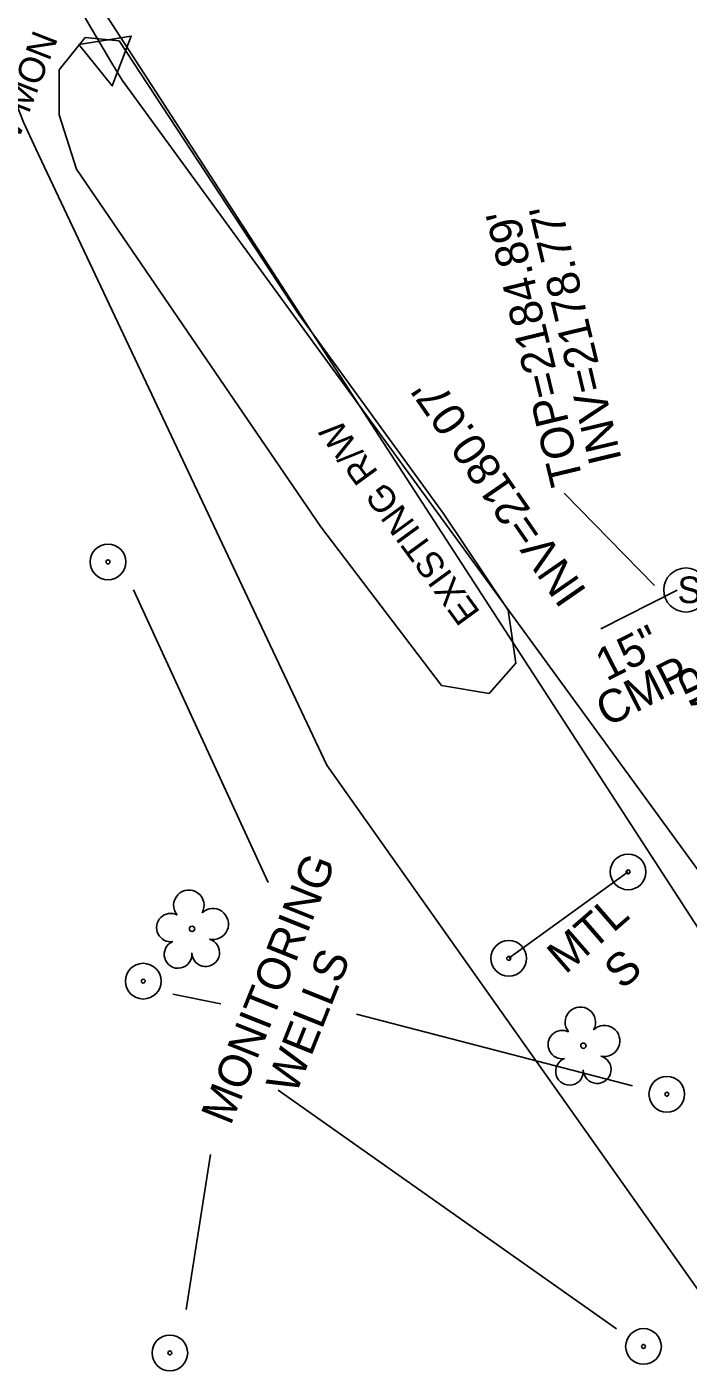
# Model space of a CAD drawing. Extents: x 945964 to 948456, y 631061 to 636061.
# Drawn here: x 946773.8 to 946854.6, y 633631 to 633795.4 of the extents above; entities that cross this region are included whole.
import ezdxf

# ---------------------------------------------------------------- set-up
doc = ezdxf.new("R2010")
doc.units = 0
for name, color, linetype in [('Exist Other Culture Fence Line', 7, 'Continuous'), ('Exist Other Culture Located Object CELL', 7, 'Continuous'), ('Exist Other Culture Located Object Leader', 7, 'Continuous'), ('Exist Other Culture Located Object Text', 7, 'Continuous'), ('Exist Other Culture Sign CELL', 7, 'Continuous'), ('Exist Other Culture Sign Text', 7, 'Continuous'), ('Exist Right of Way Line', 7, 'Continuous'), ('Exist Right of Way Line Text', 7, 'Continuous'), ('Exist Right of Way Monument CELL', 7, 'Continuous'), ('Exist Right of Way Monument Text', 7, 'Continuous'), ('Exist Structure Minor Pipes CMP 15 Inch', 7, 'Continuous'), ('Exist Structure Minor Pipes CMP 15 Inch Invert', 7, 'Continuous'), ('Exist Structure Minor Pipes CMP 15 Inch Text', 7, 'Continuous'), ('Exist Structure Minor Storm Sewer Manhole CELL', 7, 'Continuous'), ('Exist Structure Minor Storm Sewer Manhole Leader', 7, 'Continuous'), ('Exist Structure Minor Storm Sewer Manhole Text', 7, 'Continuous'), ('Exist Utilities Water UG Line SUE', 7, 'Continuous'), ('Exist Vegetation Tree CELL', 7, 'Continuous'), ('Exist Vegetation Woods Line', 7, 'Continuous'), ('Old_Level_4', 7, 'Continuous')]:
    doc.layers.add(name, color=color, linetype=linetype)

# ---------------------------------------------------------------- blocks, each defined once
blk = doc.blocks.new('EXIST STRUCTURE MINOR STORM SEWER MANHOLE')
at = {"layer": 'Exist Structure Minor Storm Sewer Manhole CELL'}
blk.add_circle((0, 0), 0.0539, dxfattribs=at)
blk.add_text('S', height=0.065, dxfattribs=at).set_placement((-0.0206, -0.032))

msp = doc.modelspace()

# ---------------------------------------------------------------- linework, layer by layer
at = {"layer": 'Exist Other Culture Fence Line'}
msp.add_lwpolyline([(946878.27, 633607.67), (946888.64, 633643.47), (946880.77, 633649.9), (946866.85, 633668.33), (946820.19, 633740.22), (946774.6, 633810.54), (946747.06, 633866.82), (946715.89, 633963.4), (946695.94, 634031.44), (946673.26, 634115.84), (946613.35, 634334.02), (946562.75, 634516.44)], dxfattribs=at)
at = {"layer": 'Exist Other Culture Located Object CELL'}
for centre, radius in [((946783.68, 633730.09), 2.18), ((946783.68, 633730.09), 0.24), ((946787.99, 633678.88), 2.18), ((946787.99, 633678.88), 0.24), ((946851.97, 633665.07), 2.18), ((946851.97, 633665.07), 0.24), ((946849.12, 633634.26), 2.18), ((946849.12, 633634.26), 0.24)]:
    msp.add_circle(centre, radius, dxfattribs=at)
at = {"layer": 'Exist Other Culture Located Object Leader'}
for points in [[(946786.79, 633726.7), (946803.26, 633690.93)], [(946791.6, 633677.3), (946797.46, 633676.12)], [(946847.77, 633666.08), (946814.04, 633674.83)], [(946845.82, 633636.4), (946804.48, 633665.58)], [(946793.25, 633638.79), (946796.19, 633657.69)]]:
    msp.add_lwpolyline(points, dxfattribs=at)
at = {"layer": 'Exist Other Culture Sign CELL'}
for centre, radius in [((946847.24, 633692.23), 2.18), ((946847.24, 633692.23), 0.24), ((946832.65, 633681.67), 2.18), ((946832.65, 633681.67), 0.24), ((946791.24, 633633.47), 2.18), ((946791.24, 633633.47), 0.24)]:
    msp.add_circle(centre, radius, dxfattribs=at)
at = {"layer": 'Exist Right of Way Line'}
msp.add_lwpolyline([(946785.42, 633788.92), (946866.73, 633677.44)], dxfattribs=at)
for centre, radius, start, end in [((947279.22, 634088.29), 577.46, 202.76129, 211.22713), ((948848.33, 632890.69), 2096.28, 158.90258, 198.31343)]:
    msp.add_arc(centre, radius, start, end, dxfattribs=at)
at = {"layer": 'Exist Right of Way Monument CELL'}
msp.add_line((946783.62, 633791.96), (946783.62, 633791.96), dxfattribs=at)
msp.add_lwpolyline([(946780.1, 633793.29), (946786.53, 633794.32), (946784.2, 633788.24)], close=True, dxfattribs=at)
at = {"layer": 'Exist Structure Minor Pipes CMP 15 Inch'}
msp.add_line((946853.25, 633726.64), (946843.9, 633721.9), dxfattribs=at)
at = {"layer": 'Exist Structure Minor Storm Sewer Manhole Leader'}
msp.add_lwpolyline([(946850.48, 633727.2), (946839.42, 633738.47)], dxfattribs=at)
at = {"layer": 'Exist Utilities Water UG Line SUE'}
msp.add_lwpolyline([(946885.48, 633607.31), (946857.92, 633638.18), (946810.43, 633705.26), (946774.88, 633780.55), (946773.35, 633783.79), (946747.51, 633849.62), (946734.48, 633879.25), (946712.81, 633944.6), (946701.3, 633998.92), (946703.12, 634056.04), (946710.69, 634080.44), (946738.48, 634116.01), (946775.16, 634148.01), (946829.92, 634190.2), (946881.2, 634227.62), (946932.03, 634251.13), (946980.62, 634279.25), (947003.27, 634299.27), (947064.64, 634327.09), (947107, 634352.54), (947145.27, 634394.7)], dxfattribs=at)
at = {"layer": 'Exist Vegetation Tree CELL'}
for p, q in [((946793.95, 633685.27), (946793.95, 633685.27)), ((946841.78, 633670.99), (946841.78, 633670.99))]:
    msp.add_line(p, q, dxfattribs=at)
for centre in [(946793.95, 633685.27), (946841.78, 633670.99)]:
    msp.add_circle(centre, 0.326, dxfattribs=at)
for centre, radius, start, end in [((946793.56, 633688.15), 1.86, 330.1651, 219.7134), ((946791.34, 633685.43), 1.73, 62.6636, 279.3457), ((946796.5, 633685.86), 1.9, 257.1011, 134.1999), ((946792.24, 633682.15), 1.69, 111.5671, 6.231), ((946795.62, 633682.37), 1.7, 181.2822, 74.56), ((946841.4, 633673.86), 1.86, 330.1651, 219.7134), ((946844.33, 633671.58), 1.9, 257.1011, 134.1999), ((946839.18, 633671.14), 1.73, 62.6636, 279.3457), ((946840.08, 633667.87), 1.69, 111.5671, 6.231), ((946843.46, 633668.09), 1.7, 181.2822, 74.56)]:
    msp.add_arc(centre, radius, start, end, dxfattribs=at)
at = {"layer": 'Exist Vegetation Woods Line'}
msp.add_lwpolyline([(946793.98, 633757.39), (946779.84, 633778.05), (946777.72, 633784.71), (946777.72, 633790.19), (946780.91, 633794.14), (946785.04, 633793.73), (946807, 633760.32), (946824.64, 633736.04), (946832.59, 633724.19), (946833.51, 633717.74), (946830.26, 633714.03), (946824.44, 633715), (946809.69, 633734.37), (946793.98, 633757.39)], dxfattribs=at)
at = {"layer": 'Old_Level_4'}
msp.add_line((946847.24, 633692.23), (946832.65, 633681.67), dxfattribs=at)

# ---------------------------------------------------------------- block references
at = {"layer": 'Exist Structure Minor Storm Sewer Manhole CELL', "xscale": 50, "yscale": 50}
msp.add_blockref('EXIST STRUCTURE MINOR STORM SEWER MANHOLE', (946854.3, 633726.66), dxfattribs=at)

# ---------------------------------------------------------------- texts
at = {"layer": 'Exist Other Culture Located Object Text'}
for s, p in [('MONITORING ', (946798.65, 633661.14)), ('  WELLS', (946805.51, 633662.13))]:
    msp.add_text(s, height=4, rotation=68.2175, dxfattribs=at).set_placement(p)
at = {"layer": 'Exist Other Culture Sign Text'}
for s, p in [('MTL', (946839.57, 633679.63)), ('S', (946846.53, 633677.74))]:
    msp.add_text(s, height=4, rotation=41.0799, dxfattribs=at).set_placement(p)
at = {"layer": 'Exist Right of Way Line Text'}
msp.add_text('EXISTING R/W', height=3.2, rotation=126.109, dxfattribs=at).set_placement((946829.26, 633723.92))
at = {"layer": 'Exist Right of Way Monument Text'}
msp.add_text('R/W MON', height=3.2, rotation=68.6933, dxfattribs=at).set_placement((946770.53, 633775.89))
at = {"layer": 'Exist Structure Minor Pipes CMP 15 Inch Invert'}
for s, rotation, p in [("INV=2178.77'", 103.3959, (946846.47, 633742.58)), ("INV=2180.07'", 124.6966, (946842.29, 633726.5))]:
    msp.add_text(s, height=4, rotation=rotation, dxfattribs=at).set_placement(p)
at = {"layer": 'Exist Structure Minor Pipes CMP 15 Inch Text'}
for s, rotation, p in [('15"', 26.8574, (946844.6, 633715.46)), ('CMP', 26.8574, (946844.64, 633709.87)), ('15" CMP', 115.6984, (946865.73, 633699.33))]:
    msp.add_text(s, height=4, rotation=rotation, dxfattribs=at).set_placement(p)
at = {"layer": 'Exist Structure Minor Storm Sewer Manhole Text'}
msp.add_text("TOP=2184.89'", height=4, rotation=103.5576, dxfattribs=at).set_placement((946841.77, 633739.93))

doc.saveas('drawing.dxf')
